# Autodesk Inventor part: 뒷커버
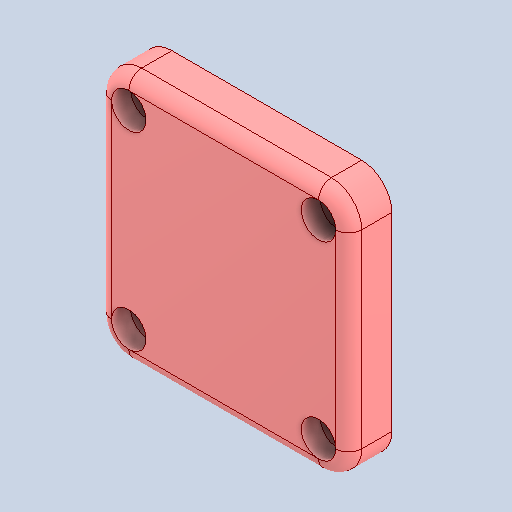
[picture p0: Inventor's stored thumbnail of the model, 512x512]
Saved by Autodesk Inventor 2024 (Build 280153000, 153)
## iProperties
Created: 2026-01
Part Number: 뒷커버
Material: 알루미늄 6061
Document SubType Name: Modeling
Designer: 2-10
Density: 2.7 g/cm^3
Appearance: 기본값
Sending System: Autodesk Inventor 2026
Preprocessor: ST-DEVELOPER v20.1
Author: jhkim
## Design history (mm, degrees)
node "뒷커버1"
node "솔리드2"
node "솔리드1"
